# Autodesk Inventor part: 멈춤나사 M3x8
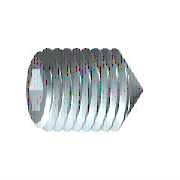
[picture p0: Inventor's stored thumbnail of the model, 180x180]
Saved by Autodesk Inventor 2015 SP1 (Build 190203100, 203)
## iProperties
IsCustomPart: 1
Created: 2012-02
Part Number: 멈춤나사 M3x8
Material: 강철, 연강
Description: 6각 소켓 머리 없는 멈춤 나사
Document SubType Name: Modeling
Standard: KS B 1028
Designer: test
Standards Organization: KS
Language: ko-KR
Size Designation: 원추점 M3x8
Categories: <MemberInstance><Categories><Category DisplayName="조임쇠" InternalName="e4da775c-781d-43d5-af7c-5136215cf5a6" Mnemonic="FSTN"><Category DisplayName="볼트" InternalN
Density: 1 g/cm^3
Appearance: 강철
Author: test
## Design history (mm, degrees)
sketch "스케치1"
  geometry: L1 (0, 0)-(5.5, 0); L2 (8, 0.866)-(8, 1.5); L3 (8, 1.5)-(0, 1.5); L4 (8, 0.866)-(6, 0.866); L5 (6, 0.866)-(5.5, 0); L6 (0, -0.3)-(0, 1.8) reference; L7 (0, 1.5)-(0, 0)
  constraints: 13 end point, 3 parallel, 1 collinear, 1 perpendicular, 1 point on line
  dimensions: "d0" = 2 distance of L2.start L4.end (= INTI); "d1" = 60 deg angle of L5 L1; "d2" = 3 diameter of L3 L1 (= NND); "d3" = 1.73205 diameter of L4 L1 (= 1.1547 x SW); "d5" = 8 distance from line of L2 L3.end (= NLG)
revolve "본체" sketch "스케치1" stored, may be unused: angle "d6" = 90 deg
sketch "스케치2"
  geometry: L1 (-0.433, 0.75)-(0.433, 0.75); L2 (0.433, 0.75)-(0.866, 0); L3 (0.866, 0)-(0.433, -0.75); L4 (0.433, -0.75)-(-0.433, -0.75); L5 (-0.433, -0.75)-(-0.866, 0); L6 (-0.866, 0)-(-0.433, 0.75); 3 further points
  constraints: 12 end point, 1 coincident, 1 horizontal, 13 other
extrude "슬롯" join sketch "스케치2" taper "d7" = 0 deg; stored distance "d21" = 10
workaxis "Work Axis1"
workplane "Work Plane1"
sketch "스케치4"
  geometry: L1 (0, 0.15)-(-1.35, 1.5) reference; L2 (0, -0.15)-(-1.35, -1.5) reference; L3 (-1.35, -1.5)-(0.15, 0); L4 (-1.35, 1.5)-(0.15, 0); 2 further points
  constraints: 4 end point, 1 coincident, 1 collinear, 1 horizontal alignment
body "Solid1"
feature "스레드" dims "d12" = 8 (= NLG), "d13" = 0
chamfer "모따기1" distance "d8" = 1.35 (computed from NND, SPD, FAWI); stored, may be unused: angle "d9" = 45 deg (= FAWI), second distance "d34" = 1.35 (computed from NND, SPD, FAWI)
chamfer "모따기2" distance "d10" = 0.30673 (= -0.5 x GD1 + 0.5 x NND); stored, may be unused: angle "d11" = 45 deg (= FAWI), second distance "d35" = 0.30673 (= -0.5 x GD1 + 0.5 x NND)
other parameters: "NND" = 3 [user parameter; used in 5 equation terms], "NLG" = 8 [user parameter; used in 2 equation terms], "INTI" = 2 [user parameter; used in 1 equation term], "FAWI" = 45 deg [user parameter; used in 4 equation terms], "SW" = 1.5 [user parameter; used in 2 equation terms], "GD1" = 2.38655 (= THREADDIA - 1.2269 x PTC) [user parameter; used in 2 equation terms], "d4" = 0, "FAWI1" = 45 deg [user parameter], "SPD" = 0.3 [user parameter; used in 2 equation terms], "d36" = 0, "d37" = 0, "GUL" = 0.30673 (= 0.61345 x PTC) [user parameter], "TOA" = 30 deg [user parameter], "THREADDIA" = 3 [user parameter; used in 1 equation term], "PTC" = 0.5 [user parameter; used in 4 equation terms], "GAL" = 0.30673 (= 0.61345 x PTC) [user parameter], "E0" = 1.7325 (= 1.155 x SW) [user parameter]
